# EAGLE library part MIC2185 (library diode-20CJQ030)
MICREL's MIC2185 Low Voltage Synchronous Boost PWM Control IC General Description: Micrel?s MIC2185 is a high efficiency synchronous boost PWM control IC. With its wide input voltage range of 2.9V to 14V, the MIC2185 can be used to efficiently boost voltages in 1- or 2-cell Li Ion battery powered applications, as well as fixed 3.3V and 5V systems. Its powerful 5? output drivers allow the MIC2185 to supply large output currents with the selection of the proper external MOSFETs. With it's fixed frequency PWM architecture, and easily synchronized drive, the MIC2185 is ideal for noise-sensitive telecommunications applications. The nominal 400kHz operating frequency of the MIC2185 can be divided by two, allowing the device to be externally synchronized to frequencies below 400kHz. The MIC2185 also features a low current shutdown mode and a programmable undervoltage lockout. A skipped pulse mode of operation can be manually set to achieve higher efficiencies at light load conditions. The MIC2185 is available in a 16 pin SOIC package and 16 pin QSOP package with an ambient temperature operating range from -40°C to 85°C. Features: Input voltage range: 2.9V to 14V 95% efficiency Oscillator frequency of 200kHz/400kHz Frequency sync to 600kHz 0.5µA shutdown current Two 5Ohm output drivers Front edge blanking PWM current mode control Cycle-by-cycle current limiting Frequency foldback protection Adjustable under-voltage lockout Precision 1.245V reference output 16 pin SOIC narrow body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
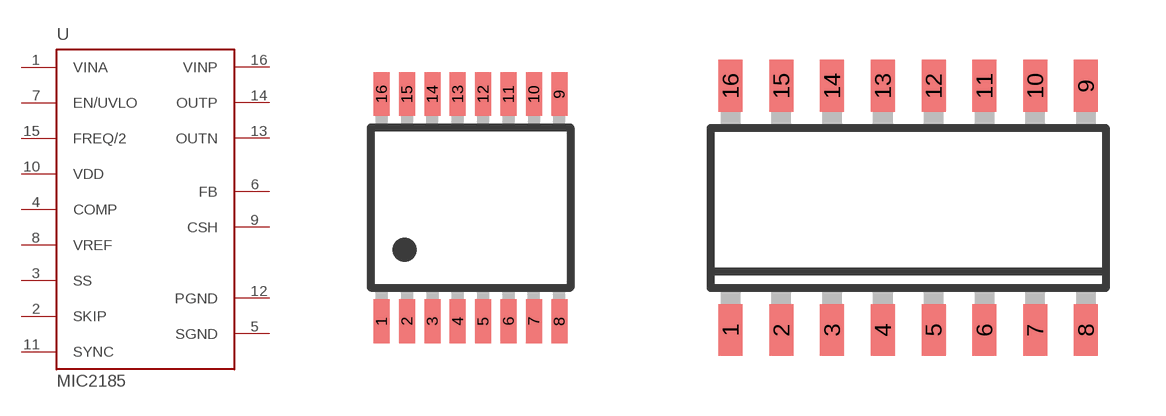
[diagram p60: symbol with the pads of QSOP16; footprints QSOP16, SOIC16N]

Designator prefix U

## MIC2185QSOP16  [QSOP16]
1  VINA  pwr
2  SKIP  in
3  SS  in
4  COMP  out
5  SGND  pwr
6  FB  in
7  EN/UVLO  in
8  VREF  out
9  CSH  in
10  VDD  in
11  SYNC  in
12  PGND  pwr
13  OUTN  out
14  OUTP  out
15  FREQ/2  in
16  VINP  in

## MIC2185QSOIC16  [SOIC16N]
Pads as for QSOP16

## Footprint QSOP16 (pad centres in mm)
QSOP-16 E.g. MIC2185
smd 0.4 x 1.1: 1 -2.223,-2.84; 2 -1.587,-2.84; 3 -0.953,-2.84; 4 -0.318,-2.84; 5 0.318,-2.84; 6 0.953,-2.84; 7 1.587,-2.84; 8 2.223,-2.84; 9 2.223,2.84; 10 1.587,2.84; 11 0.953,2.84; 12 0.318,2.84; 13 -0.318,2.84; 14 -0.953,2.84; 15 -1.587,2.84; 16 -2.223,2.84

## Footprint SOIC16N (pad centres in mm)
SMALL OUTLINE INTEGRATED CIRCUIT
smd 0.6 x 1.3: 1 -4.445,-3.05; 2 -3.175,-3.05; 3 -1.905,-3.05; 4 -0.635,-3.05; 5 0.635,-3.05; 6 1.905,-3.05; 7 3.175,-3.05; 8 4.445,-3.05; 9 4.445,3.05; 10 3.175,3.05; 11 1.905,3.05; 12 0.635,3.05; 13 -0.635,3.05; 14 -1.905,3.05; 15 -3.175,3.05; 16 -4.445,3.05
